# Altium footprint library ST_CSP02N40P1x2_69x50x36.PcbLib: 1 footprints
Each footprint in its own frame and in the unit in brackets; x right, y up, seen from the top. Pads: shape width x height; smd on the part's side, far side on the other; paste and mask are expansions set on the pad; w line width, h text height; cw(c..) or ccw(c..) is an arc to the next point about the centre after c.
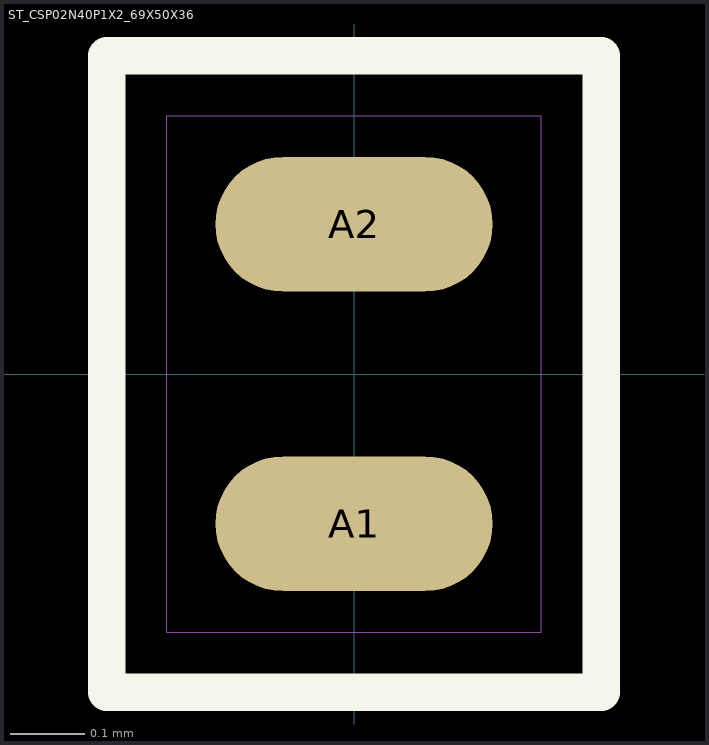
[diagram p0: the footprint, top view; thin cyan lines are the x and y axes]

## ST_CSP02N40P1X2_69X50X36 [mm] "ST_CSP02N40P1X2_69X50X36"
pads (2):
  oval 0.37x0.18 smd mask+0.04: A1(0,-0.2) A2(0,0.2)
Top Overlay:
  lines w0.05: -0.33,-0.425 -0.33,0.425 0.33,0.425 0.33,-0.425 -0.33,-0.425
Mechanical 6:
  lines w0: -0.25,-0.345 0.25,-0.345 0.25,0.345 -0.25,0.345 -0.25,-0.345
Mechanical 7:
  lines w0: -0.25,-0.345 -0.25,0.345 0.25,0.345 0.25,-0.345 -0.25,-0.345
3D body: height 0.41, standoff 0.06, extent -0.25,-0.345 0.25,0.345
